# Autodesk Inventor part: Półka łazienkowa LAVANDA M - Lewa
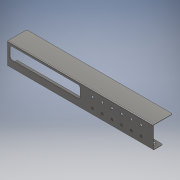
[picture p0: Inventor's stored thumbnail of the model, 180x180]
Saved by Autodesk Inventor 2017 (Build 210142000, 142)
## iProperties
Created: 2019-07
Part Number: Półka łazienkowa LAVANDA M - Lewa
Material: Ogólny
Document SubType Name: Modeling
Designer: Marcel
Density: 1 g/cm^3
Appearance: Domyślna
Author: Marcel
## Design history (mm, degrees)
derived "Półka łazienkowa LAVANDA M - Lewa.iam"
node "Bryła1"
node "Uchwyt na ręcznik 1 - 60 cm.ipt:1" dims "d0" = 10
node "Kapselek.ipt:1" dims "d0" = 10
node "Kapselek.ipt:2" dims "d0" = 10
